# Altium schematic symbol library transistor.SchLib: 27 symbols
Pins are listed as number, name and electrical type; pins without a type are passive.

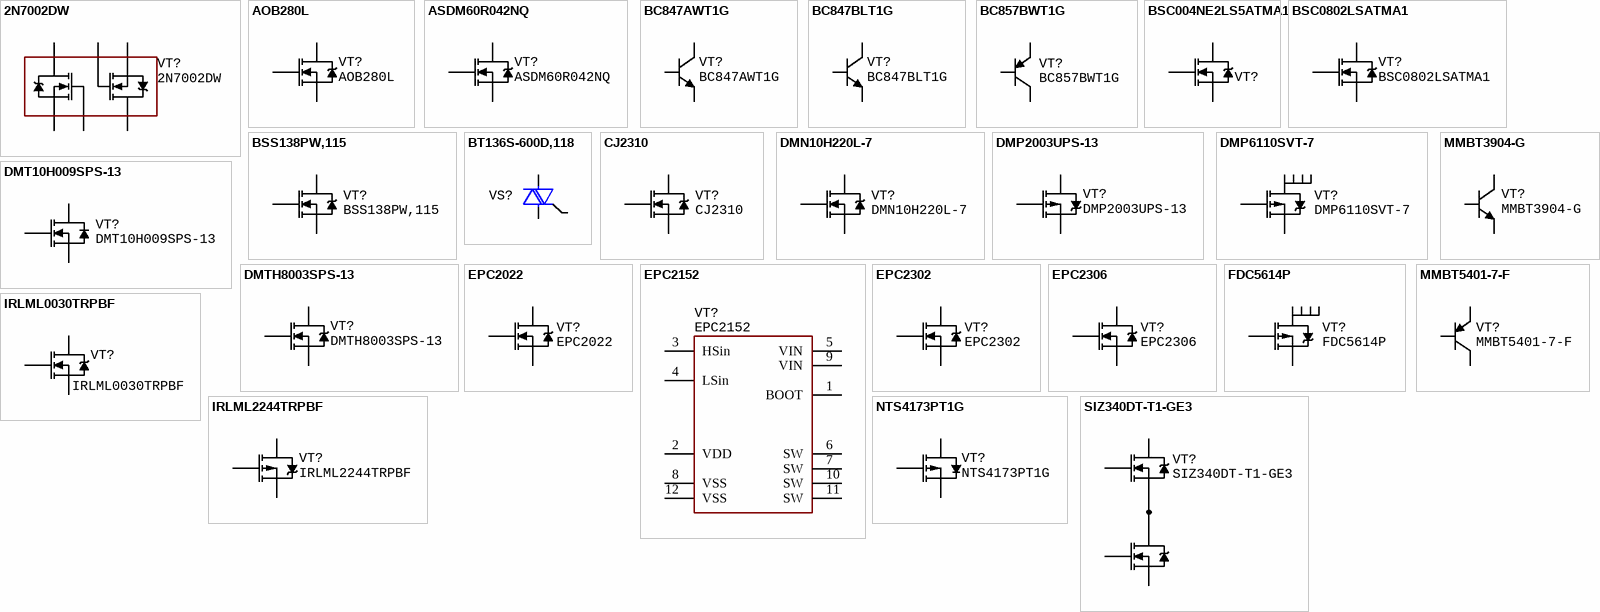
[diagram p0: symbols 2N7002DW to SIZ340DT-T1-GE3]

## 2N7002DW
designator VT?
Dual N-MOSFET, 60V, 7.5 Ohms, 2.6 nC, 1.3W, 115mA, SOT-363, -55...+150°C; Manufacturer: ON Semiconductor; Manufacturer: ON Semiconductor / Fairchild
footprint SC70-6
pins: 1 S, 2 G, 3 D, 4 S, 5 G, 6 D

## AOB280L
designator VT?
N-MOSFET, 80V, 2.2 mOhms, 224 nC, 2.1W, 20.5A, D2Pak, -55...+175°C; Manufacturer: Alpha & Omega; Manufacturer: Alpha & Omega Semiconductor
footprint D2PAK
pins: 1 G, 2 D, 3 S

## ASDM60R042NQ
designator VT?
N-MOSFET, 60V, 4.4 mOhms, 34 nC, 2.5W, 116A, TDSON-8, -55...+150°C; Manufacturer: Ascend
footprint 8-TDSON (pitch 1.3 mm, power pad)
pins: 1 G, 2 D, 3 S

## BC847AWT1G
designator VT?
NPN, 45V, 100mA, 100MHz, SC-70, -55...+150°C; Manufacturer: ON Semiconductor
footprint SC-70
pins: 1 B, 2 E, 3 C

## BC847BLT1G
designator VT?
NPN, 45V, 100mA, 100MHz, SOT-23, -55...+150°C; Manufacturer: ON Semiconductor
footprint SOT23
pins: 1 B, 2 E, 3 C

## BC857BWT1G
designator VT?
PNP, 45V, 100mA, 100MHz, SC-70, -55...+150°C; Manufacturer: ON Semiconductor
footprint SC-70
pins: 1 B, 2 E, 3 C

## BSC004NE2LS5ATMA1
designator VT?  (value not drawn)
N-MOSFET, 25V, 0.45 mOhms, 238 nC, 2.5W, 100A, TDSON-8, -55...+150°C; Manufacturer: Infineon; Manufacturer Part Number: BSC0802LSATMA1
footprint 8-TDSON (pitch 1.3 mm, power pad)
pins: 1 G, 2 D, 3 S

## BSC0802LSATMA1
designator VT?
N-MOSFET, 100V, 3.5 mOhms, 37 nC, 2.5W, 100A, TDSON-8, -55...+150°C; Manufacturer: Infineon
footprint 8-TDSON (pitch 1.3 mm, power pad)
pins: 1 G, 2 D, 3 S

## BSS138PW,115
designator VT?
N-MOSFET, 60V, 300mA, 1.6 Ohm, 0.8nC, 50pF, SC-70, -55...+150°C; Manufacturer: Nexperia
footprint SC-70
pins: 1 G, 2 S, 3 D

## BT136S-600D,118
designator VS?  (value not drawn)
TRIAC, 600V, 4A, 1.4V, 10mA, Dpak, -40...+125°C; Manufacturer: WeEn; Manufacturer: International Rectifier; Manufacturer Part Number: IRLML2244TRPBF
footprint DPAK
pins: 1, 2, 3

## CJ2310
designator VT?
N-MOSFET, 60V, 3A, 125 mOhms, 6nC, SOT23-6, -55...+150°C; Manufacturer: Jiangsu Tech
footprint SOT23
pins: 1 G, 2 S, 3 D

## DMN10H220L-7
designator VT?
N-MOSFET, 100V, 220 mOhms, 8.3 nC, 1.3W, 1.6A, SOT-23, -55...+150°C; Manufacturer: Diodes
footprint SOT23
pins: 1 G, 2 S, 3 D

## DMP2003UPS-13
designator VT?
P-MOSFET, 20V, 150A, 1,7mOhm, 177nC, 570pF, 8-TDSON, -55...+150°C; Manufacturer: Diodes
footprint 8-TDSON (pitch 1.3 mm, power pad)
pins: 1 G, 2 D, 3 S

## DMP6110SVT-7
designator VT?
P-MOSFET, 60V, 7.3A, 105mOhm, 17.2nC, 969pF, SOT-23-6, -55...+150°C; Manufacturer: Diodes
footprint SOT23-6 (pitch 0.95 mm)
pins: 1 D, 2 D, 3 G, 4 S, 5 D, 6 D

## DMT10H009SPS-13
designator VT?
N-MOSFET, 100V, 8.5 mOhms, 30 nC, 2.5W, 80A, TDSON-8, -55...+150°C; Manufacturer: Diodes
footprint 8-TDSON (pitch 1.3 mm, power pad)
pins: 1 G, 2 D, 3 S

## DMTH8003SPS-13
designator VT?
N-MOSFET, 80V, 3.9 mOhms, 124 nC, 2.5W, 100A, TDSON-8, -55...+175°C; Manufacturer: Diodes
footprint 8-TDSON (pitch 1.3 mm, power pad)
pins: 1 G, 2 D, 3 S

## EPC2022
designator VT?
GaN, 100V, 3.2 mOhms, 13 nC, 90A, case 6.05x2.3 mm, -40...+150°C; Manufacturer: EPC
footprint EPC2022 (GaN, 6.05x2.3)
pins: 1 G, 2 D, 3 S

## EPC2152
designator VT?
GaN, 100V, 1.8 mOhms, 29 nC, 101A, case 5x3 mm, -40...+150°C; Manufacturer: EPC
footprint EPC2152
pins: 1 BOOT, 2 VDD, 3 HSin, 4 LSin, 5 VIN, 6 SW, 7 SW, 8 VSS, 9 VIN, 10 SW, 11 SW, 12 VSS

## EPC2302
designator VT?
GaN, 100V, 1.8 mOhms, 29 nC, 101A, case 5x3 mm, -40...+150°C; Manufacturer: EPC
footprint EPC2302 (QFN3x5 100V Full Die)
pins: 1 G, 2 S, 3 D

## EPC2306
designator VT?
GaN, 100V, 3.8 mOhms, 29 nC, 48A, case 5x3 mm, -40...+150°C; Manufacturer: EPC
footprint EPC2306 (QFN3x5 100V Half Die)
pins: 1 G, 2 S, 3 D

## FDC5614P
designator VT?
P-MOSFET, 60V, 3A, 70mOhm, 10nC, 969pF, SOT-23-6, -55...+150°C; Manufacturer: MSKSEMI
footprint SOT23-6 (pitch 0.95 mm)
pins: 1 D, 2 D, 3 G, 4 S, 5 D, 6 D

## IRLML0030TRPBF
designator VT?
N-MOSFET, 30V, 27 mOhms, 2.6 nC, 1.3W, 5.3A, SOT-23, -55...+150°C; Manufacturer: Infineon; Manufacturer: International Rectifier
footprint SOT23
pins: 1 G, 2 S, 3 D

## IRLML2244TRPBF
designator VT?
P-MOSFET, 20V, 4.3A, 54mOhm, 6.9nC, 570pF, SOT-23, -55...+150°C; Manufacturer: Infineon Technologies; Manufacturer: International Rectifier
footprint SOT23
pins: 1 G, 2 S, 3 D

## MMBT3904-G
designator VT?
NPN, 40V, 200mA, 300MHz, SOT-23, -55...+150°C; Manufacturer: Comchip
footprint SOT23
pins: 1 B, 2 E, 3 C

## MMBT5401-7-F
designator VT?
PNP, 150V, 200mA, 300MHz, SOT-23, -55...+150°C; Manufacturer: ON Semiconductor; Manufacturer: Diodes Zetex
footprint SOT23
pins: 1 B, 2 E, 3 C

## NTS4173PT1G
designator VT?
P-MOSFET, 30V, 1.3A, 150mOhm, 4.8nC, 570pF, SC-70, -55...+150°C; Manufacturer: ON Semiconductor
footprint SC-70
pins: 1 G, 2 S, 3 D

## SIZ340DT-T1-GE3
designator VT?
N-MOSFET, 30V, 5.1 mOhms, 19 nC, 40A, DFN-8, -55...+150°C; Manufacturer: Vishay
footprint SIZ340DT-T1-GE3 (3x3 mm, pitch 0.65 mm, power pad)
pins: D1, G1, G2, S1, S2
